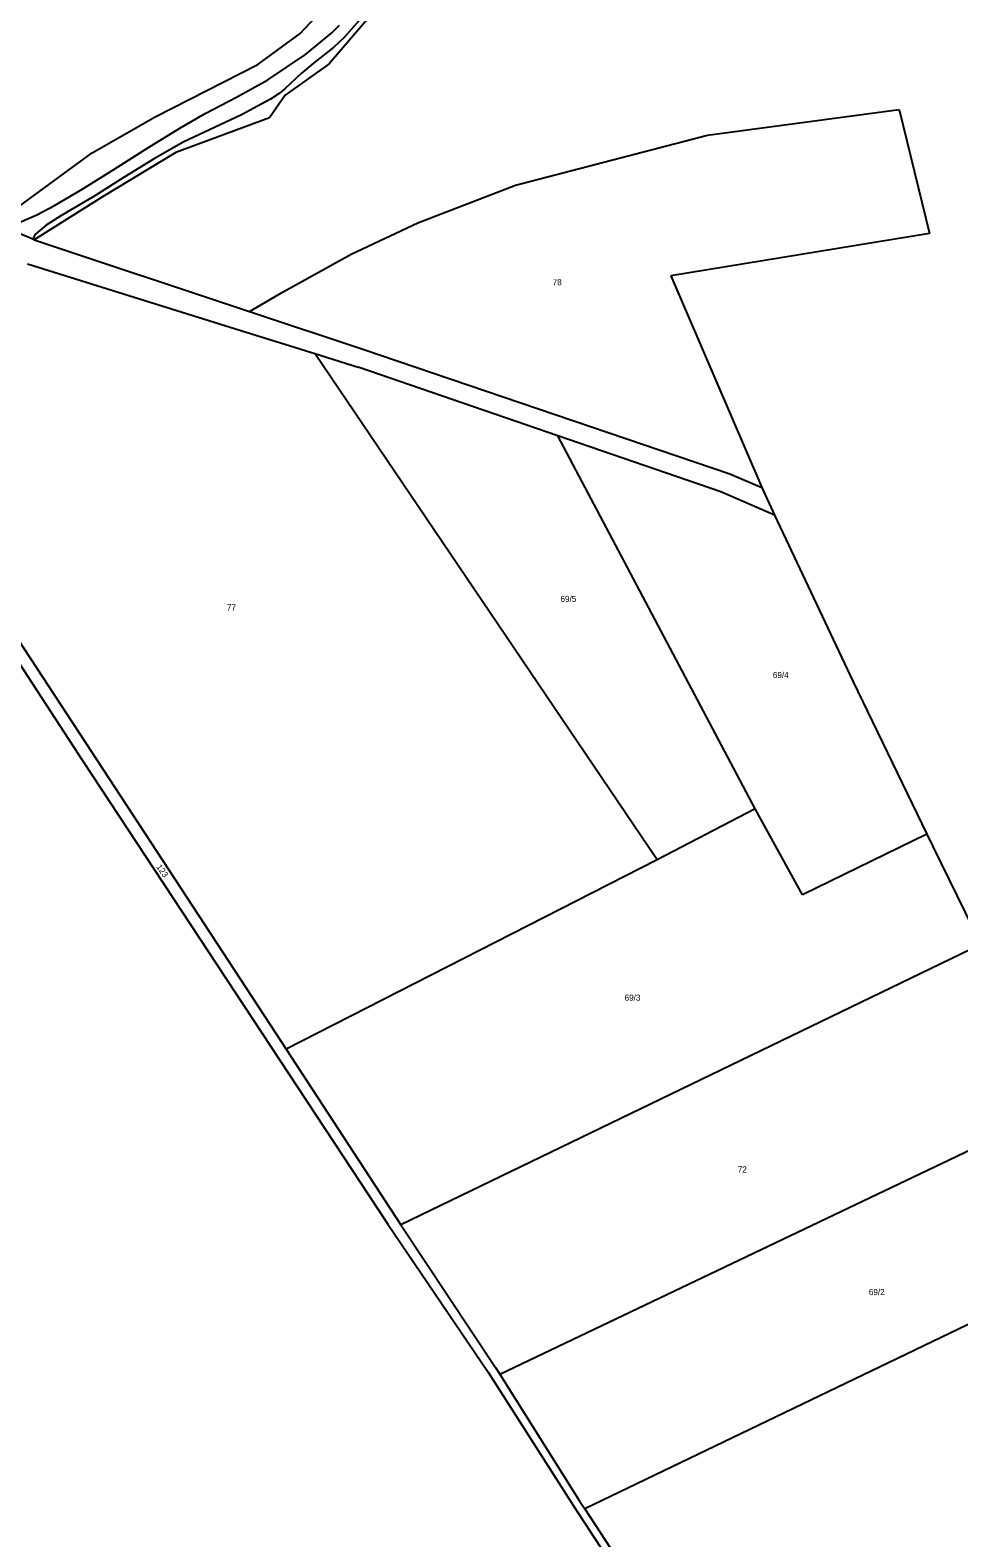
# Model space of a CAD drawing. Extents: x -752500 to -750336, y -1035826 to -1033500.
# Drawn here: x -750892.2 to -750633.1, y -1035440.1 to -1035019.2 of the extents above; entities that cross this region are included whole.
import ezdxf

# ---------------------------------------------------------------- set-up
doc = ezdxf.new("R2010")
doc.units = 0
for name, color, linetype in [('Hranice kat_území', 7, 'Continuous'), ('Hranice parcel', 7, 'Continuous'), ('Parcelní čísla', 7, 'Continuous')]:
    doc.layers.add(name, color=color, linetype=linetype)

msp = doc.modelspace()

# ---------------------------------------------------------------- linework, layer by layer
at = {"layer": 'Hranice kat_území'}
for p, q in [((-750781.93, -1034997.22), (-750808.77, -1035028.55)), ((-750808.77, -1035028.55), (-750821.04, -1035037.35)), ((-750821.04, -1035037.35), (-750825.43, -1035043.68)), ((-750703.19, -1035048.53), (-750649.72, -1035041.28)), ((-750649.72, -1035041.28), (-750641.2, -1035075.94)), ((-750825.43, -1035043.68), (-750851.53, -1035053.36)), ((-750756.76, -1035062.46), (-750703.19, -1035048.53)), ((-750851.53, -1035053.36), (-750872, -1035065.71)), ((-750872, -1035065.71), (-750891.06, -1035077.67)), ((-750784.02, -1035072.94), (-750756.76, -1035062.46)), ((-750802.56, -1035081.72), (-750784.02, -1035072.94)), ((-750891.06, -1035077.67), (-750830.94, -1035097.68)), ((-750641.2, -1035075.94), (-750713.44, -1035087.79)), ((-750821.62, -1035092.2), (-750802.56, -1035081.72)), ((-750713.44, -1035087.79), (-750688.06, -1035146.89)), ((-750830.94, -1035097.68), (-750821.62, -1035092.2)), ((-750688.06, -1035146.89), (-750684.47, -1035154.53)), ((-750684.47, -1035154.53), (-750662.59, -1035200.92)), ((-750662.59, -1035200.92), (-750641.95, -1035243.61)), ((-750641.95, -1035243.61), (-750640.28, -1035247.07)), ((-750640.28, -1035247.07), (-750626.88, -1035274.39))]:
    msp.add_line(p, q, dxfattribs=at)
at = {"layer": 'Hranice parcel'}
for p, q in [((-750816.84, -1035020.15), (-750802.11, -1035004.29)), ((-750828.63, -1035028.73), (-750816.84, -1035020.15)), ((-750857.32, -1035043.41), (-750828.63, -1035028.73)), ((-750874.87, -1035053.45), (-750857.32, -1035043.41)), ((-750901.86, -1035073.17), (-750874.87, -1035053.45)), ((-750891.45, -1035077.51), (-750898.92, -1035074.4)), ((-750891.06, -1035077.67), (-750891.45, -1035077.51)), ((-750892.88, -1035084.41), (-750833.35, -1035102.98)), ((-750830.94, -1035097.68), (-750799.07, -1035108.28)), ((-750833.35, -1035102.98), (-750812.7, -1035109.45)), ((-750799.07, -1035108.28), (-750696.95, -1035143.05)), ((-750717.21, -1035250.8), (-750812.7, -1035109.45)), ((-750812.7, -1035109.45), (-750800.69, -1035113.22)), ((-750744.96, -1035132.4), (-750800.69, -1035113.22)), ((-750689.89, -1035236.52), (-750744.96, -1035132.4)), ((-750699.48, -1035148.05), (-750744.96, -1035132.4)), ((-750696.95, -1035143.05), (-750688.06, -1035146.89)), ((-750684.47, -1035154.53), (-750699.48, -1035148.05)), ((-750902.74, -1035184.42), (-750877.61, -1035223.09)), ((-750900.52, -1035181.7), (-750876.9, -1035217.73)), ((-750876.9, -1035217.73), (-750823.55, -1035299.39)), ((-750877.61, -1035223.09), (-750792.36, -1035352.54)), ((-750689.89, -1035236.52), (-750717.21, -1035250.8)), ((-750676.68, -1035260.56), (-750689.89, -1035236.52)), ((-750641.95, -1035243.61), (-750676.68, -1035260.56)), ((-750717.21, -1035250.8), (-750820.76, -1035303.65)), ((-750626.88, -1035274.39), (-750788.73, -1035352.67)), ((-750823.55, -1035299.39), (-750820.76, -1035303.65)), ((-750820.76, -1035303.65), (-750788.73, -1035352.67)), ((-750761.16, -1035394.35), (-750602.3, -1035318.55)), ((-750553.02, -1035343.26), (-750737.45, -1035432.01)), ((-750792.36, -1035352.54), (-750764.38, -1035393.81)), ((-750788.73, -1035352.67), (-750762.33, -1035392.48)), ((-750764.38, -1035393.81), (-750740.57, -1035431.12)), ((-750762.33, -1035392.48), (-750761.16, -1035394.35)), ((-750761.16, -1035394.35), (-750738.8, -1035429.95)), ((-750740.57, -1035431.12), (-750710.58, -1035476.86)), ((-750738.8, -1035429.95), (-750737.45, -1035432.01)), ((-750737.45, -1035432.01), (-750708.72, -1035475.83))]:
    msp.add_line(p, q, dxfattribs=at)
for points in [[(-750798.27, -1035014.08), (-750804.62, -1035021.34), (-750807.43, -1035023.95), (-750813.15, -1035028.42), (-750816.56, -1035031.28), (-750821.12, -1035035.55), (-750822.71, -1035036.89), (-750825.13, -1035038.47), (-750833.24, -1035042.81), (-750849.48, -1035050.45), (-750857.72, -1035055.23), (-750865.97, -1035060.25), (-750874.16, -1035065.47), (-750883.65, -1035071.01), (-750887.7, -1035073.65), (-750890.61, -1035076.05), (-750891, -1035076.56), (-750891.45, -1035077.51)], [(-750898.92, -1035074.4), (-750897.41, -1035073.81), (-750890.32, -1035070.72), (-750885.35, -1035068.16), (-750877.46, -1035063.5), (-750868.82, -1035058.04), (-750859.66, -1035052.19), (-750850.44, -1035046.52), (-750843.34, -1035042.48), (-750834.62, -1035037.88), (-750825.86, -1035033.03), (-750815.39, -1035025.94), (-750807.98, -1035019.93), (-750805.82, -1035017.82)]]:
    msp.add_lwpolyline(points, dxfattribs=at)

# ---------------------------------------------------------------- texts
at = {"layer": 'Parcelní čísla'}
for s, p in [('78', (-750746.39, -1035090.39)), ('77', (-750837.3, -1035181.21)), ('69/5', (-750744.21, -1035178.8)), ('69/4', (-750684.95, -1035200.05)), ('69/3', (-750726.31, -1035290.12)), ('72', (-750694.75, -1035338.1)), ('69/2', (-750658.17, -1035372.31))]:
    msp.add_text(s, height=1.7, dxfattribs=at).set_placement(p)
msp.add_text('123', height=1.7, rotation=304.642, dxfattribs=at).set_placement((-750857.05, -1035252.77))

doc.saveas('drawing.dxf')
